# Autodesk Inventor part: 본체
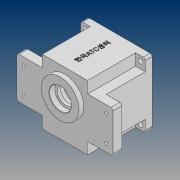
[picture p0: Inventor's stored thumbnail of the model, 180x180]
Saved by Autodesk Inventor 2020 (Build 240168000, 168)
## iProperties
Created: 2020-07
Part Number: 본체
Material: 일반
Document SubType Name: Modeling
Designer: PC312-
Density: 1 g/cm^3
Appearance: 기본값
Author: PC312-
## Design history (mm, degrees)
sketch "스케치1"
  geometry: L1 (-47, 47)-(47, 47); L2 (47, 47)-(47, -47); L3 (47, -47)-(-47, -47); L4 (-47, -47)-(-47, 47); L5 (-47, 47)-(47, -47); L6 (47, 47)-(-47, -47); 1 further point
  constraints: 12 end point, 2 midpoint, 2 parallel, 1 horizontal, 1 perpendicular
  dimensions: "d0" = 94 distance of L2.end L3.end; "d1" = 94 distance of L1.end L2.end
extrude "돌출1" new body sketch "스케치1" distance "d2" = 10; taper "d3" = 0 deg
sketch "스케치2"
  geometry: L1 (-33, 47)-(33, 47); L2 (33, 47)-(33, -47); L3 (33, -47)-(-33, -47); L4 (-33, -47)-(-33, 47); L5 (47, 47)-(-47, 47) reference; L6 (-47, -47)-(47, -47) reference; L7 (-47, 47)-(-47, -47) reference; L8 (-47, 30)-(47, 30); L9 (47, 30)-(47, -30); L10 (47, -30)-(-47, -30); L11 (-47, -30)-(-47, 30); L12 (47, -47)-(47, 47) reference; 8 further points
  constraints: 16 end point, 4 parallel, 3 collinear, 2 horizontal, 2 midpoint, 2 perpendicular, 1 horizontal alignment, 1 point on line, 1 vertical alignment
  dimensions: "d4" = 66 distance of L2.end L3.end; "d5" = 60 distance of L8.end L9.end
extrude "돌출2" join sketch "스케치2" distance "d6" = 70; taper "d7" = 0 deg
sketch "스케치3"
  geometry: L1 (-70, 30)-(70, 30); L2 (70, 30)-(70, -30); L3 (70, -30)-(-70, -30); L4 (-70, -30)-(-70, 30); 3 further points
  constraints: 8 end point, 2 midpoint, 2 parallel, 1 horizontal, 1 horizontal alignment, 1 perpendicular, 1 vertical alignment
  dimensions: "d8" = 140 distance between parallel lines of L2 L4; "d9" = 60 distance between parallel lines of L3 L1
extrude "돌출3" join sketch "스케치3" distance "d10" = 13; taper "d11" = 0 deg
sketch "스케치4"
  geometry: C1 r 43 at (0, 0); 1 further point
  constraints: 1 centre point, 1 coincident
  dimensions: "d12" = 86 diameter of C1
extrude "돌출4" cut sketch "스케치4" distance "d13" = 9; taper "d14" = 0 deg
sketch "스케치5"
  geometry: C1 r 40 at (0, 0); 1 further point
  constraints: 1 centre point, 1 coincident
  dimensions: "d15" = 80 diameter of C1
sketch "스케치6"
  geometry: C1 r 27.5 at (0, 11); 1 further point
  constraints: 1 centre point, 1 vertical alignment
  dimensions: "d16" = 55 diameter of C1; "d17" = 11 distance of point (0, 0) C1.centre
extrude "돌출5" join sketch "스케치6" distance "d18" = 7; taper "d19" = 0 deg
extrude "돌출6" cut sketch "스케치5" distance "d20" = 62; taper "d21" = 0 deg
sketch "스케치8"
  geometry: C1 r 27.5 at (0, 0) reference; C2 r 16 at (0, 0); 1 further point
  constraints: 1 centre point, 1 coincident
  dimensions: "d22" = 32 diameter of C2
extrude "돌출7" cut sketch "스케치8" distance "d23" = 8.3; taper "d24" = 0 deg
node "작업 평면1"
sketch "스케치12"
  geometry: C1 r 16 at (0, 0) reference; C2 r 17.5 at (0, 0); 1 further point
  constraints: 1 centre point, 1 coincident
  dimensions: "d32" = 35 diameter of C2
extrude "돌출10" join sketch "스케치12" stored distance "d33" = 4.7; taper "d34" = 0 deg
sketch "스케치13"
  geometry: C1 r 16 at (0, 0) reference; C2 r 12.5 at (0, 0); 1 further point
  constraints: 1 centre point, 1 coincident
  dimensions: "d35" = 25 diameter of C2
extrude "돌출11" cut sketch "스케치13" distance "d36" = 4.7; taper "d37" = 0 deg
sketch "스케치16"
  geometry: C1 r 17.5 at (0, 0) reference; C2 r 21 at (0, 0); 1 further point
  constraints: 1 centre point, 1 coincident
  dimensions: "d39" = 42 diameter of C2
extrude "돌출12" join sketch "스케치16" stored distance "d40" = 4.7; taper "d41" = 0 deg
sketch "스케치17"
  geometry: C1 r 21 at (0, 0) reference; C2 r 17.5 at (0, 0); 1 further point
  constraints: 1 centre point, 1 coincident
  dimensions: "d42" = 35 diameter of C2
extrude "돌출13" cut sketch "스케치17" distance "d43" = 10; taper "d44" = 0 deg
sketch "스케치19"
  geometry: C1 r 15 at (0, -31); 1 further point
  constraints: 1 centre point, 1 vertical alignment
  dimensions: "d47" = 30 diameter of C1; "d48" = 20 distance of point (0, -11) C1.centre
extrude "돌출14" join sketch "스케치19" stored distance "d49" = 10; taper "d50" = 0 deg
sketch "스케치20"
  geometry: C1 r 11 at (0, -31); A1 r 15 centre (0, -31) between (-8.978, -18.984) and (8.978, -18.984) reference; 1 further point
  constraints: 1 centre point, 1 coincident
  dimensions: "d51" = 22 diameter of C1
extrude "돌출15" cut sketch "스케치20" distance "d52" = 7; taper "d53" = 0 deg
sketch "스케치21"
  geometry: C1 r 12.5 at (0, 0) reference; C2 r 17.5 at (0, 0); 1 further point
  constraints: 1 centre point, 1 coincident
  dimensions: "d54" = 35 diameter of C2
extrude "돌출16" cut sketch "스케치21" distance "d55" = 10; taper "d56" = 0 deg
sketch "스케치22"
  geometry: C1 r 11 at (0, 0) reference; C2 r 9.5 at (0, 0); 1 further point
  constraints: 1 centre point, 1 coincident
  dimensions: "d57" = 19 diameter of C2
extrude "돌출17" cut sketch "스케치22" distance "d58" = 3; taper "d59" = 0 deg
sketch "스케치23"
  geometry: A1 r 36 centre (0, 0) between (36, 0) and (35.772, 4.045); A2 r 4 centre (36, 0) between (36.19, 3.995) and (36.19, -3.995); A3 r 3 centre (36.333, 6.992) between (35.772, 4.045) and (39.279, 7.559); A4 r 40 centre (0, 0) between (39.279, 7.559) and (39.279, -7.559) reference; A5 r 3 centre (36.333, -6.992) between (39.279, -7.559) and (35.772, -4.045); 1 further point
  constraints: 13 point on circle, 4 centre point, 4 tangent, 1 coincident, 1 horizontal alignment
  dimensions: "d60" = 72 diameter of A1; "d61" = 8 diameter of A2; "d62" = 6 diameter of A3; "d63" = 6 diameter of A5
extrude "돌출18" join sketch "스케치23" stored distance "d64" = 3; taper "d65" = 0 deg
fillet "모깎기1" dims "d66" = 3
fillet "모깎기2" dims "d67" = 3
sketch "스케치26"
  geometry: C1 r 2.25 at (60, 19); 1 further point
  constraints: 1 centre point
  dimensions: "d70" = 4.5 diameter of C1; "d71" = 60 horizontal distance of C1.centre point (0, 0); "d72" = 19 vertical distance of C1.centre point (0, 0)
extrude "돌출19" cut sketch "스케치26" distance "d73" = 8; taper "d74" = 0 deg
sketch "스케치27"
  geometry: C1 r 2.25 at (-60, 19) reference; C2 r 5 at (-60, 19); 1 further point
  constraints: 1 centre point, 1 coincident
  dimensions: "d75" = 10 diameter of C2
extrude "돌출20" cut sketch "스케치27" distance "d76" = 5; taper "d77" = 0 deg
sketch "스케치28"
  geometry: C1 r 3.5 at (40, 40); 1 further point
  constraints: 1 centre point
  dimensions: "d84" = 7 diameter of C1; "d85" = 40 horizontal distance of C1.centre point (0, 0); "d86" = 40 horizontal distance of C1.centre point (0, 0)
extrude "돌출21" cut sketch "스케치28" extent not by distance; stored distance "d87" = 5; taper "d88" = 0 deg
node "작업 평면3"
sketch "스케치30"
  geometry: L1 (77, 80)-(-11, 80) reference; 3 further points
  constraints: 1 midpoint, 1 vertical alignment, 1 other
  dimensions: "d96" = 40 distance from line of L1 point (33, 40)
feature "엠보싱1" sketch "스케치30" dims "d5" = 60, "d97" = 0.5, "d98" = 0
chamfer "모따기2" distance "d102" = 1; stored, may be unused: second distance "d103" = 2, angle "d104" = 45 deg
chamfer "모따기3" distance "d105" = 0.8; stored, may be unused: second distance "d106" = 2, angle "d107" = 30 deg
fillet "모깎기3" dims "d108" = 1
fillet "모깎기4" dims "d109" = 1
fillet "모깎기5" dims "d110" = 3
sketch "스케치31"
  geometry: A1 r 4 centre (-36, 0) between (-36.19, -3.995) and (-36.19, 3.995) reference; A2 r 4 centre (36, 0) between (36.19, 3.995) and (36.19, -3.995) reference; 3 further points
  constraints: 2 coincident
hole "구멍1" sketch "스케치31" at (-36, 0), (36, 0) diameter "d111" = 3.242; stored, may be unused: countersink angle "d115" = 90 deg, drill point angle "d117" = 118 deg; dims "d112" = 7, "d113" = 4, "d114" = 2, "d116" = 9
node "솔리드1"
mirror "미러1"
pattern_linear "직사각형 패턴1" dims "d80" = 120
pattern_linear "직사각형 패턴2" dims "d83" = 38
pattern_linear "직사각형 패턴3" dims "d91" = 80
pattern_linear "직사각형 패턴4" dims "d94" = 80
node "작업 평면2"
feature "A9D066F2-1C7D-4E18-AEED-F7BC21143FA4" dims "d111" = 3.242, "d112" = 7, "d113" = 4, "d114" = 2, "d115" = 90 deg, "d116" = 9, "d117" = 118 deg
other parameters: "d28" = -23
